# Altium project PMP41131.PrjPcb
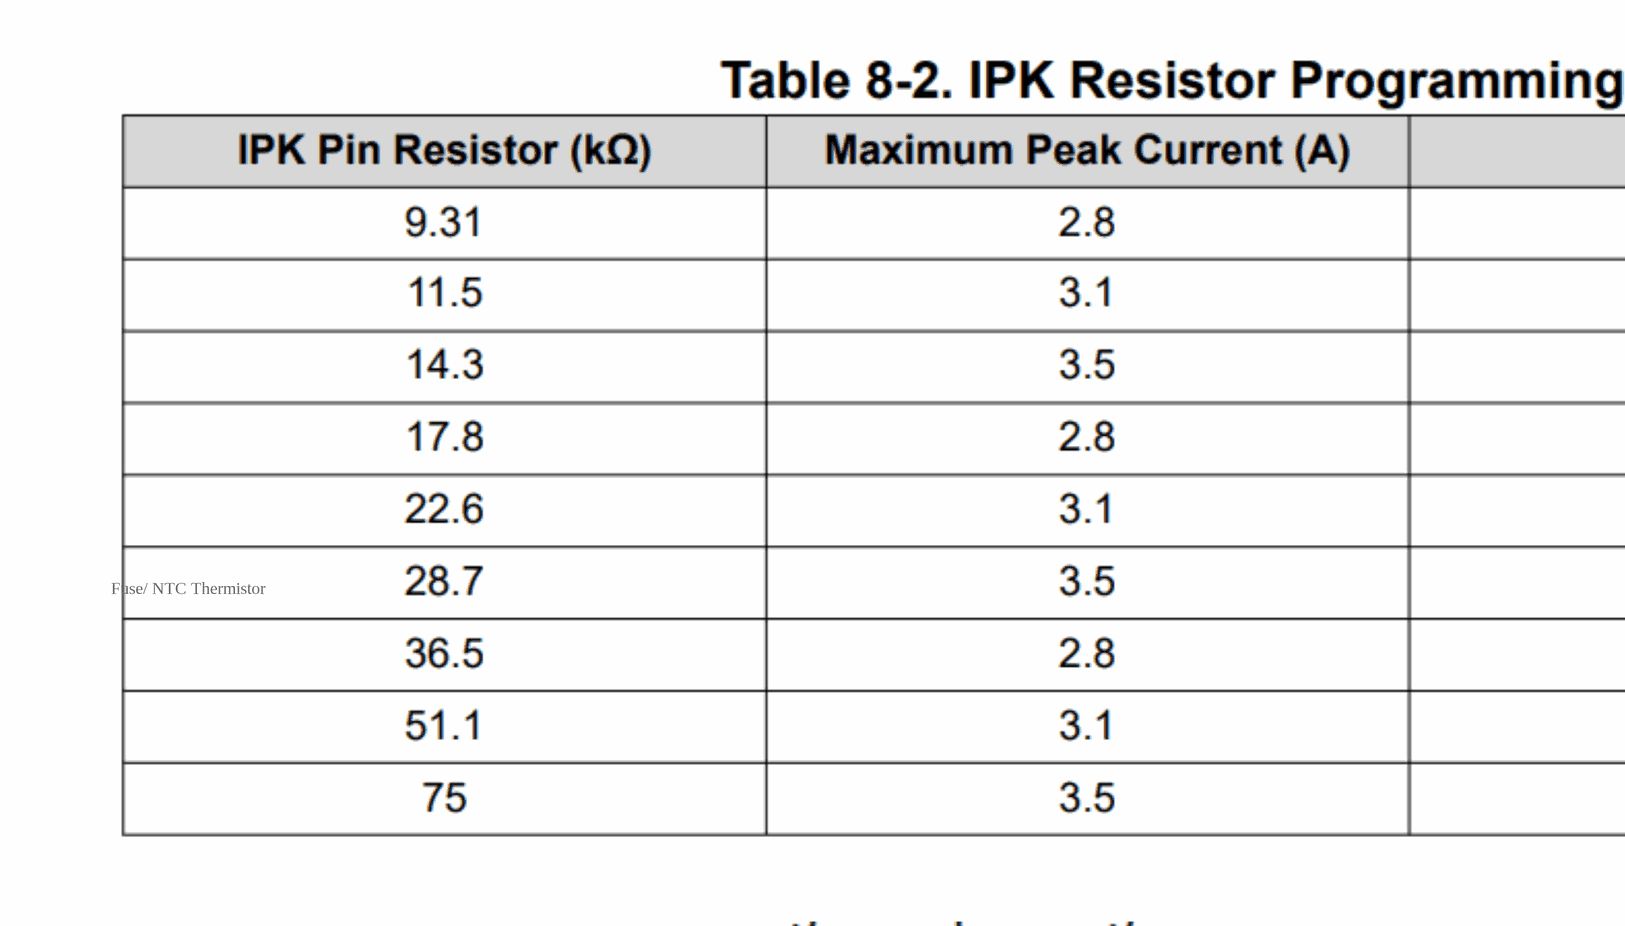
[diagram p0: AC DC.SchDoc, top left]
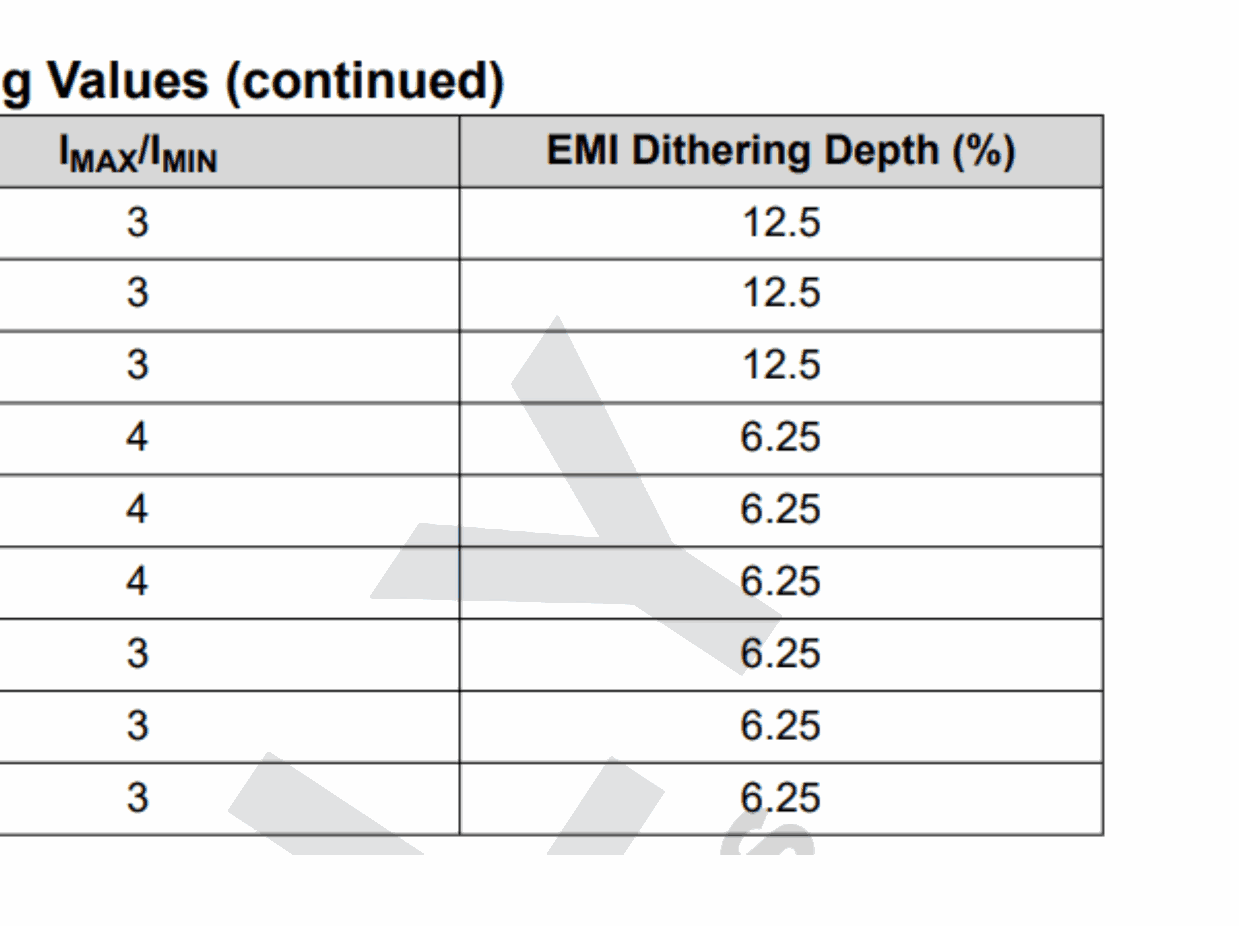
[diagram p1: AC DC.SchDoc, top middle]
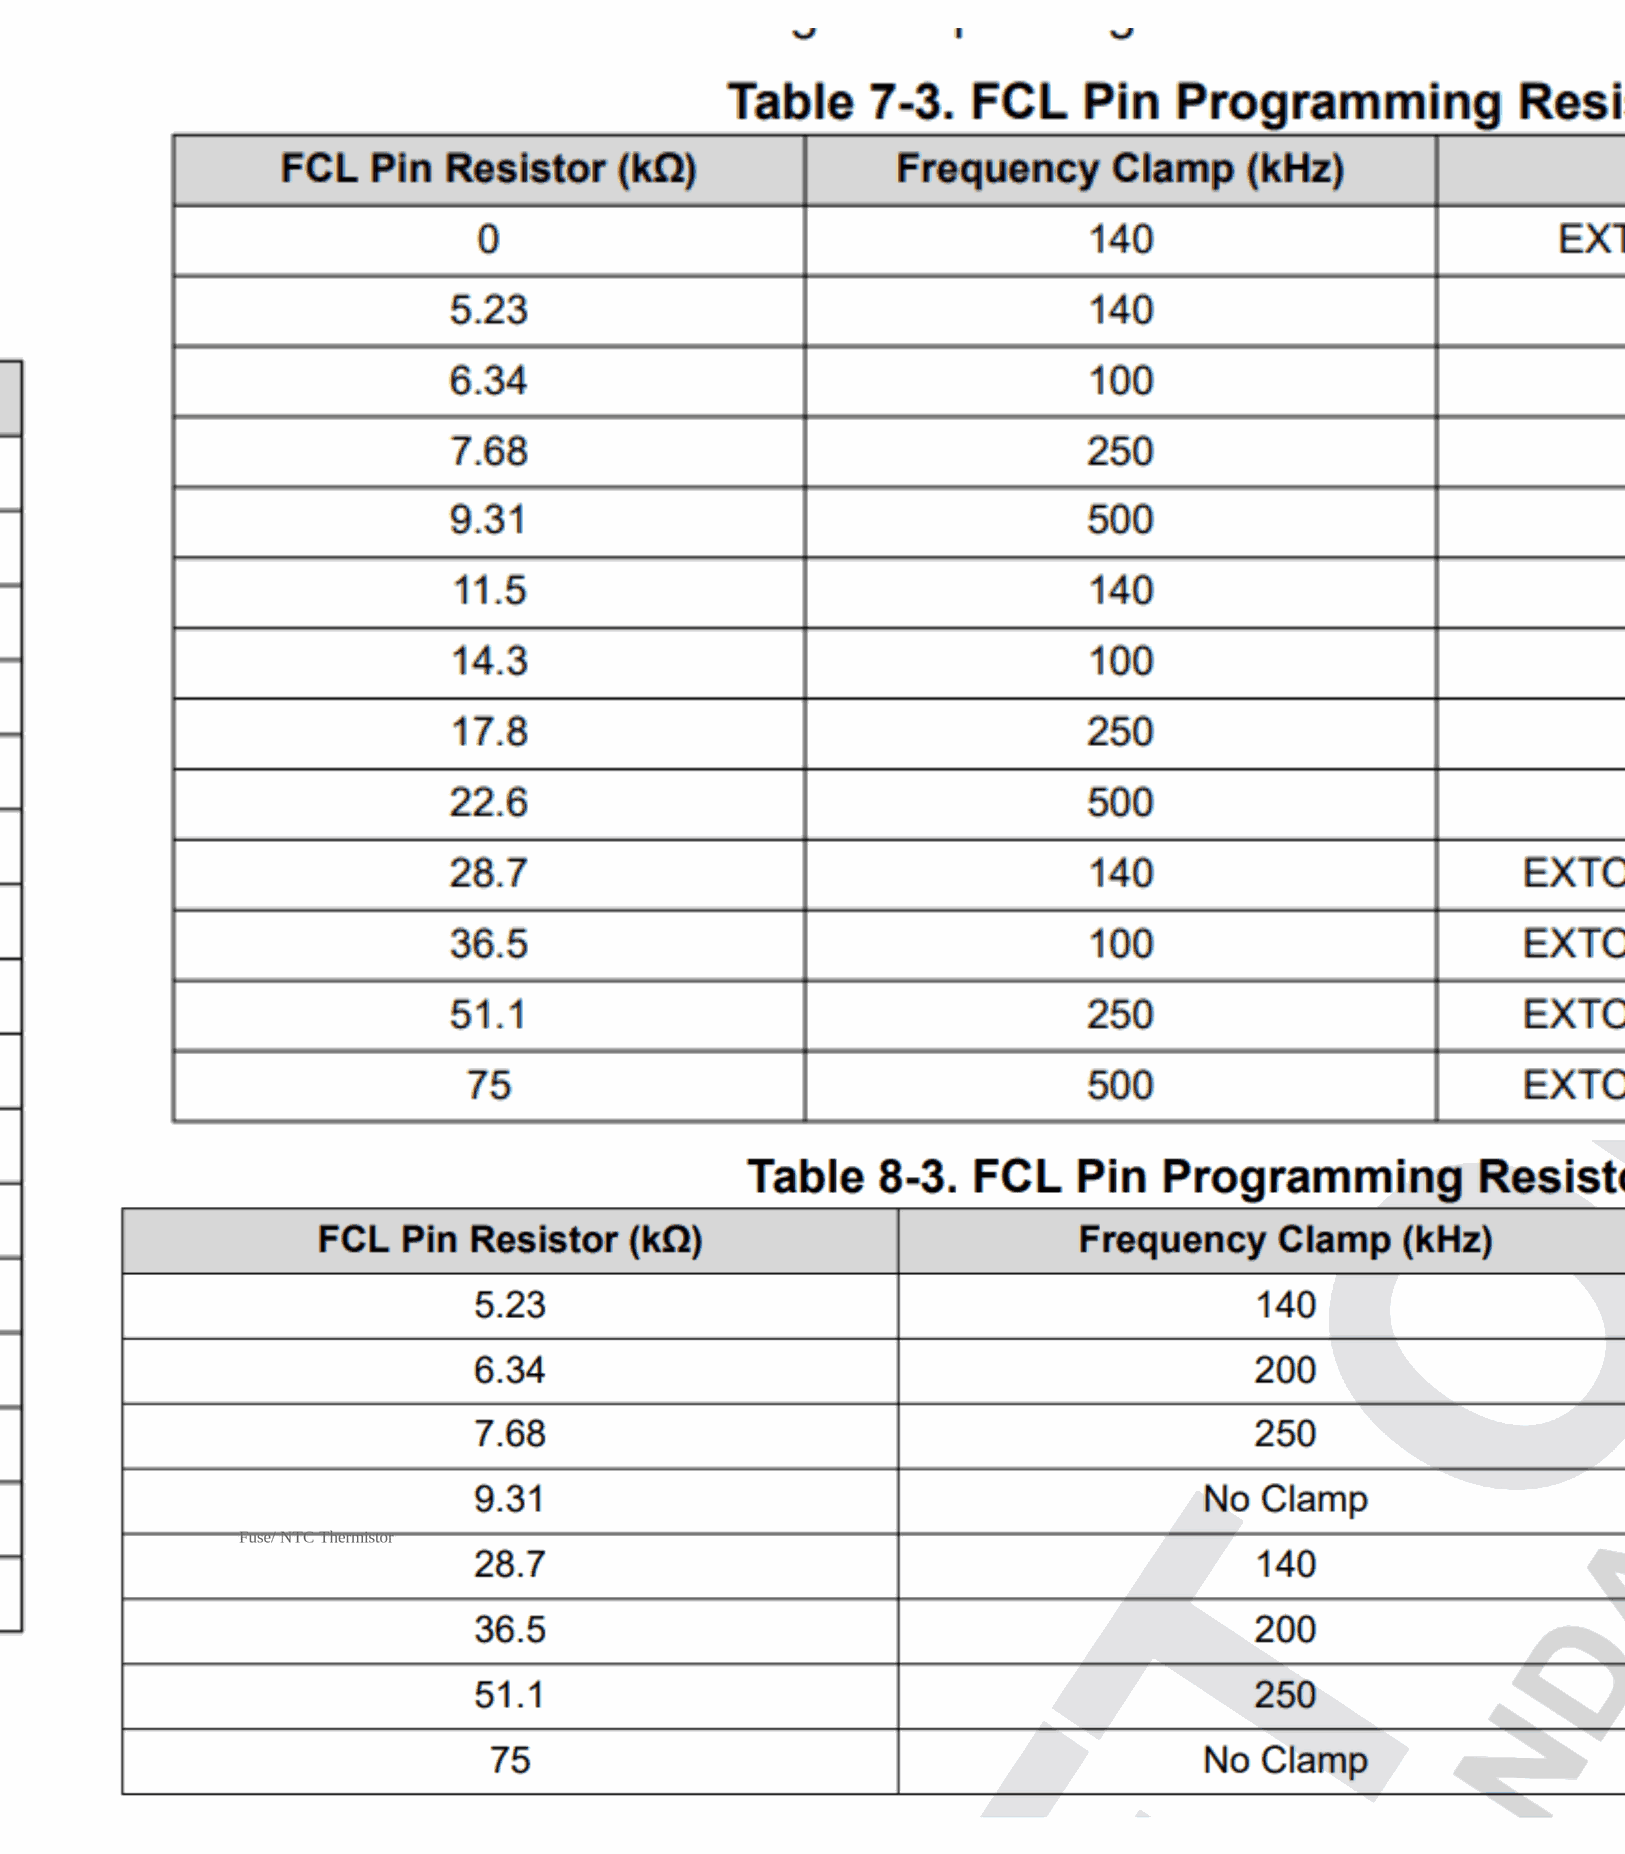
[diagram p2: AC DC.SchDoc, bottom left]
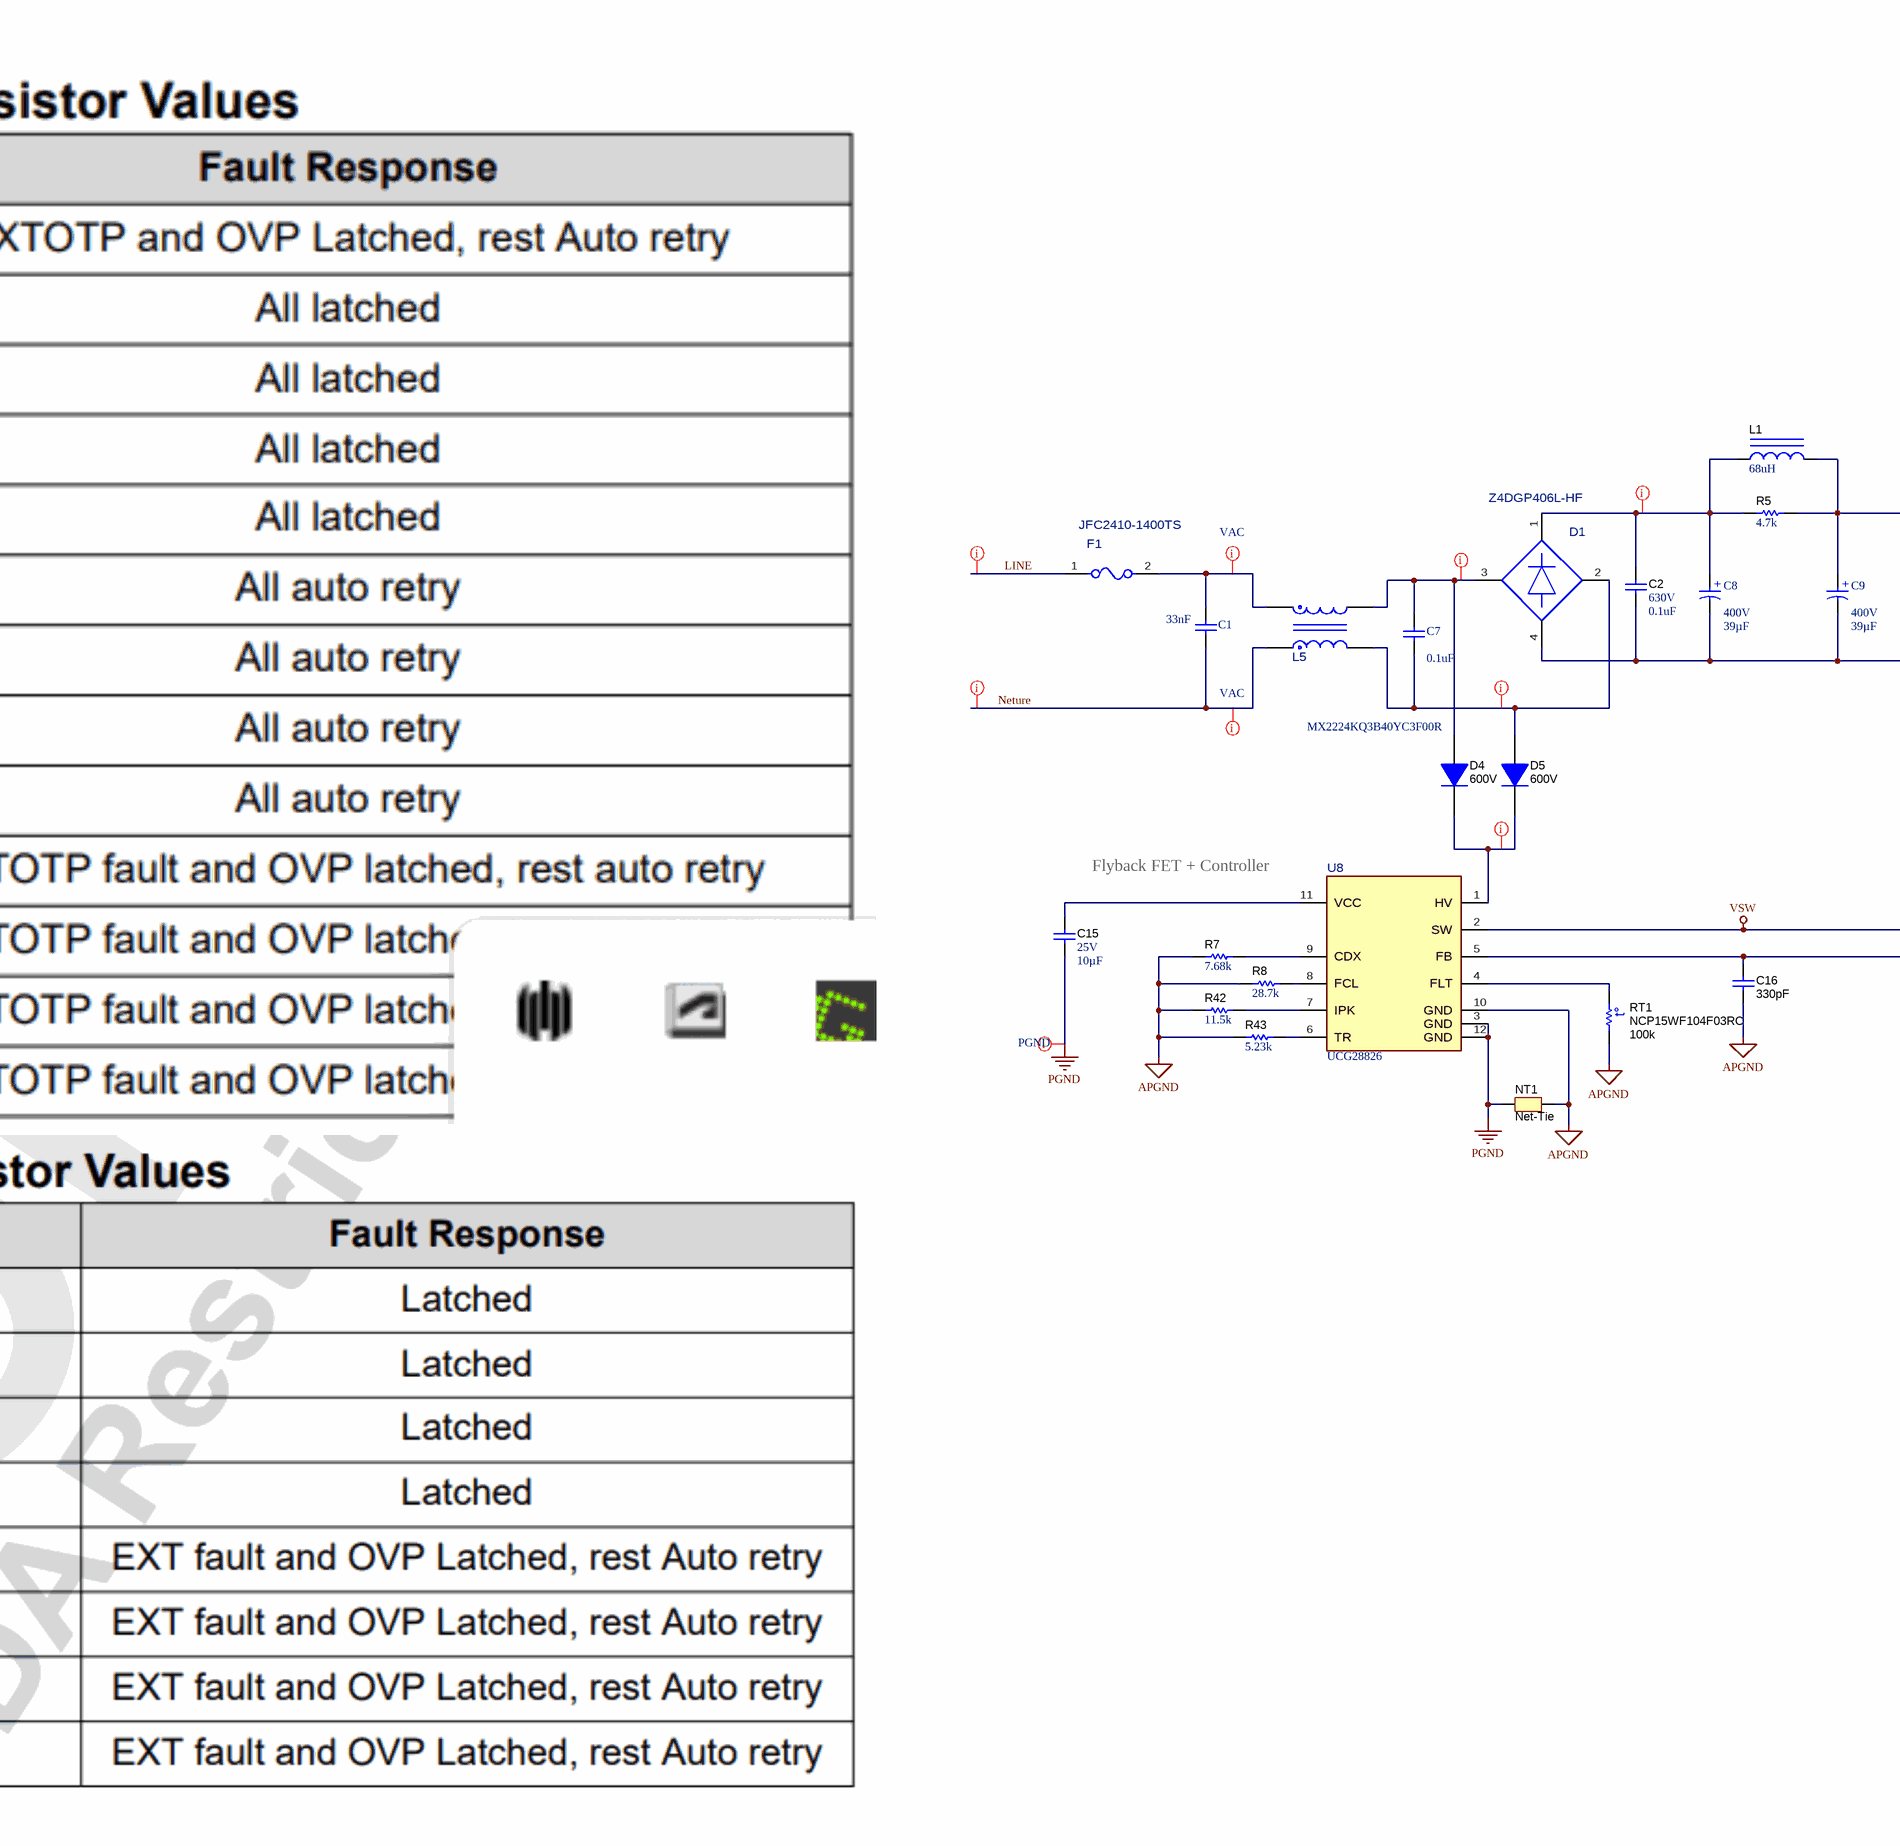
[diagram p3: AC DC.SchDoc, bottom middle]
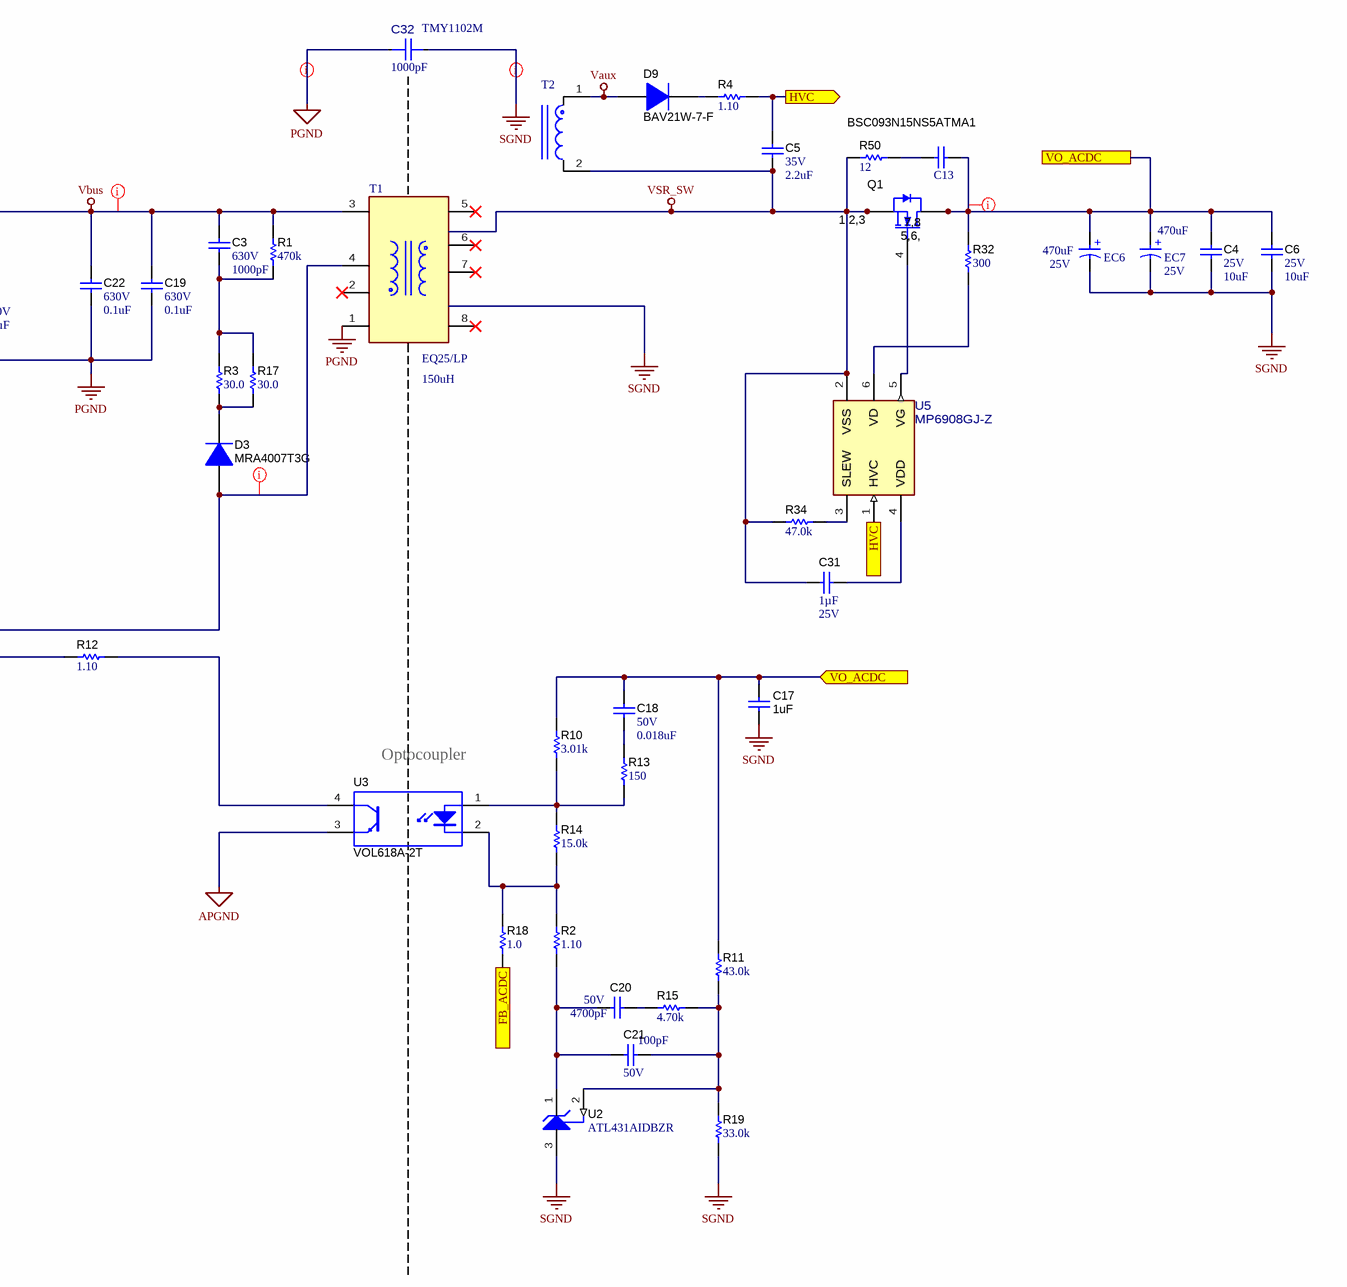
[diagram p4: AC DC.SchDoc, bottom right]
CopyrightYear: 2018; PCB_Layout: Who did the Layout?; PCB_Rev: E1; PRJ_Customer: Public Release; PRJ_Engineer: Enter name of project lead; PRJ_Number: PMP41131; PRJ_Title: Change in menu Project|Project Options|Parameters; SCH_Rev: E1; TechSupport: http://www.ti.com/support; TID: N/A
2 sheets, 93 parts. Net scope: flat (ports and power ports of the same name join across sheets).
Board file: PMP41131.PcbDoc
Sheets:
  AC DC.SchDoc
  USB Type C and PD.SchDoc

## Sheet AC DC.SchDoc
size 431 x 279 mm; Date: Not shown in title block; ApprovedBy: Not shown in title block; CheckedBy: Not shown in title block; Author: Not shown in title block; CompanyName: Not shown in title block; Engineer: Not shown in title block; Organization: Not shown in title block; Address1: Not shown in title block; Address2: Not shown in title block; Address3: Not shown in title block; Address4: Not shown in title block; DocumentNumber: 1; Revision: Use project parameter SCH_Rev; SheetNumber: 1; SheetTotal: 2; PageSetup: Record=PageOptions¦CenterHorizontal=True¦CenterVertical=True¦PrintScale=1.00¦XCorrection=1.00¦YCorrection=1.00¦PrintKind=0¦BorderSize=5000000¦LeftOffset=0¦BottomOffset=0¦Orientation=2¦PaperLength=1000¦PaperWidth=1000¦Scale=100¦PaperSource=15¦PrintQuality=600¦MediaType=1¦DitherType=10¦PaperKind=Letter¦PrintScaleMode=1

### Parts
C1  Cap_F: 33nF  [2220_280]  (hidden comment: SCC2220X333K252T)
C2  VDC_V: 630V  ValueDisplayed: 0.1uF  [1206_180]  (hidden comment: C3216X7T2W104M160AA)
C3  VDC_V: 630V  ValueDisplayed: 1000pF  [1206]  (hidden comment: GRM31BR72J102KW01L)
C4  VDC_V: 25V  ValueDisplayed: 10uF  [0805_HV]  (hidden comment: TMK212BBJ106KG-T)
C5  VDC_V: 35V  ValueDisplayed: 2.2uF  [0603]  (hidden comment: GRM188R6YA225KA12D)
C6  VDC_V: 25V  ValueDisplayed: 10uF  [0805_HV]  (hidden comment: TMK212BBJ106KG-T)
C7  value 0.1uF  PartNumber: MX2224KQ3B40YC3F00R  [XCAP DGXC 0.1UF]  (hidden comment: XCAP DGCX 0.1uF)
C8  Rated Voltage (DC): 400V  Cap_F: 39µF  [400V27uF_Laydown]  (hidden comment: 865230657014)
C9  Rated Voltage (DC): 400V  Cap_F: 39µF  [400V27uF_Laydown]  (hidden comment: 865230657014)
C13  885342207003  [WCAP-CSMH_0805_L2W1.25H0.8_Reflow]  (value not drawn)
C15  VDC_V: 25V  ValueDisplayed: 10µF  [0603S]  (hidden comment: GRM188R61E106KA73D)
C16  ValueDisplayed: 330pF  [0402S]  (hidden comment: GRM155R71H331KA01D)
C17  ValueDisplayed: 1uF  [0603S]  (hidden comment: C1608X7R1E105K080AB)
C18  VDC_V: 50V  ValueDisplayed: 0.018uF  [0402S]  (hidden comment: GRM155R71H183KA12D)
C19  VDC_V: 630V  ValueDisplayed: 0.1uF  [1206_180]  (hidden comment: C3216X7T2W104M160AA)
C20  VDC_V: 50V  ValueDisplayed: 4700pF  [0402S]  (hidden comment: GRM155R71H472KA01D)
C21  VDC_V: 50V  ValueDisplayed: 100pF  [0402S]  (hidden comment: 885012205055)
C22  VDC_V: 630V  ValueDisplayed: 0.1uF  [1206_180]  (hidden comment: C3216X7T2W104M160AA)
C31  Cap_F: 1µF  VDC_V: 25V  [0603S]  (hidden comment: CGA3E1X7R1E105K080AC)
C32  ValueDisplayed: 1000pF  [FP-TMY1102M_7854-MFG]  (hidden comment: TMY1102M)
D1  Z4DGP406L-HF  [FP-Z4DGP406L-HF_SMT_8MM1_10MM5-MFG]
D3  MRA4007T3G  [SMA]
D4  value 600V  [SOD-123]  (hidden comment: ES1JFL)
D5  value 600V  [SOD-123]  (hidden comment: ES1JFL)
D9  BAV21W-7-F  [SOD-123]
EC6  value 470uF  Voltage: 25V  [CE05.5P254L11]  (hidden comment: ECAP_LAYDOWN)
EC7  value 470uF  Voltage: 25V  [CE05.5P254L11]  (hidden comment: ECAP_LAYDOWN)
F1  JFC2410-1400TS  [FP-JFC2410-1400TS_SMT_FUSE_6MM1_2MM6-MFG]
L1  ValueDisplayed: 68uH  [MNR-6045]  (hidden comment: MNR-6045-680MTS)
L5  MDM-9070F-102  [FP-MDM-9070F-102_SMT_CMC_9MM0_7MM0-MFG]  (value not drawn)
NT1  Net-Tie  [Net-Tie_10milWide_30milLong]  (net tie, no BOM)
Q1  BSC093N15NS5ATMA1  [PG-TDSON-8]
R1  ValueDisplayed: 470k  [0805_HV]  (hidden comment: CRCW0805470KJNEA)
R2  ValueDisplayed: 1.10  [0402S]  (hidden comment: CRCW04021R10FKED)
R3  ValueDisplayed: 30.0  [1206]  (hidden comment: RC1206FR-0730RL)
R4  ValueDisplayed: 1.10  [0402S]  (hidden comment: CRCW04021R10FKED)
R5  ValueDisplayed: 4.7k  [1206]  (hidden comment: CRCW12064K70JNEA)
R7  ValueDisplayed: 7.68k  [0402S]  (hidden comment: CRCW04027K68FKED)
R8  ValueDisplayed: 28.7k  [0402S]  (hidden comment: CRCW040228K7FKED)
R10  ValueDisplayed: 3.01k  [0402S]  (hidden comment: CRCW04023K01FKED)
R11  ValueDisplayed: 43.0k  [0603]  (hidden comment: RG1608P-433-B-T5)
R12  ValueDisplayed: 1.10  [0402S]  (hidden comment: CRCW04021R10FKED)
R13  ValueDisplayed: 150  [0402S]  (hidden comment: CRCW0402150RFKED)
R14  ValueDisplayed: 15.0k  [0402S]  (hidden comment: CRCW040215K0FKED)
R15  ValueDisplayed: 4.70k  [0402S]  (hidden comment: RC0402FR-074K7L)
R17  ValueDisplayed: 30.0  [1206]  (hidden comment: RC1206FR-0730RL)
R18  ValueDisplayed: 1.0  [0402S]  (hidden comment: CRCW04021R00JNED)
R19  ValueDisplayed: 33.0k  [0603]  (hidden comment: RG1608P-333-B-T5)
R32  ValueDisplayed: 300  [0603]  (hidden comment: RC0603FR-07300RL)
R34  ValueDisplayed: 47.0k  [0603S]  (hidden comment: CRCW060347K0FKEA)
R42  ValueDisplayed: 11.5k  [0402S]  (hidden comment: CRCW040211K5FKED)
R43  ValueDisplayed: 5.23k  [0402S]  (hidden comment: CRCW04025K23FKED)
R50  ValueDisplayed: 12  [0603]  (hidden comment: CRCW060312R0JNEA)
RT1  NCP15WF104F03RC  value 100k  [0402S]
T1  EQ25/LP  value 150uH  [ATQ23.9_13.8_Remove Flywire]
T2  (no value)  [ATQ23.7_15 4+4 Pin]
U2  ATL431AIDBZR  [DBZ0003A_N]
U3  VOL618A-2T  [SOP254P1020X230-4]
U5  MP6908GJ-Z  [FP-MP6908GJ-Z_TSOT23-6-MFG]
U8  PartNumber: UCG28826  [REZ0012A-MFG]  (hidden comment: UCG28682)

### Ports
FB_ACDC (in), HVC (in), HVC (out), VO_ACDC, VO_ACDC (in)

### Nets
APGND: C16.2 NT1.2 R7.1 R8.1 R42.1 R43.1 RT1.1 U3.3(E) U8.10(GND)
PGND: C2.2 C8.2(N) C9.2(N) C15.2 C19.2 C22.2 C32.1 D1.4(-) NT1.1 T1.1 U8.3(GND) U8.12(GND)
SGND: C4.2 C6.2 C17.1 C32.2 EC6.2(N) EC7.2(N) R19.1 U2.3(ANODE)
Vaux: D9.2(A) T2.1
Vbus: C3.2 C9.1(P) C19.1 C22.1 L1.2 R1.2 R5.2 T1.3
VSR_SW: C5.2 C31.2 Q1.1(S) Q1.2(S) Q1.3(S) R34.1 R50.1 T2.2 U5.2(VSS)
VSW: D3.2(A) T1.4 U8.2(SW)
FB_ACDC: R18.1 ; port FB_ACDC
HVC: C5.1 R4.2 U5.1(HVC) ; port HVC
LINE: F1.1
Neture: C1.2 L5.3
VO_ACDC: C4.1 C6.1 C13.2 C17.2 C18.1 EC6.1(P) EC7.1(P) Q1.5(D) Q1.6(D) Q1.7(D) Q1.8(D) Q1.9(D) R10.2 R11.2 R32.1 ; port VO_ACDC
NetC1_1: C1.1 F1.2 L5.1
NetC2_1: C2.1 C8.1(P) D1.1(+) L1.1 R5.1
NetC3_1: C3.1 R1.1 R3.2 R17.2
NetC7_1: C7.1 D1.3(2_~) D4.2(A) L5.2
NetC7_2: C7.2 D1.2(1_~) D5.2(A) L5.4
NetC13_1: C13.1 R50.2
NetC15_1: C15.1 U8.11(VCC)
NetC16_1: C16.1 R12.1 U8.5(FB)
NetC18_2: C18.2 R13.2
NetC20_1: C20.1 R15.1
NetC20_2: C20.2 C21.2 R2.1 U2.1(CATHODE)
NetC21_1: C21.1 R11.1 R15.2 R19.2 U2.2(REF)
NetC31_1: C31.1 U5.4(VDD)
NetD3_1: D3.1(K) R3.1 R17.1
NetD4_1: D4.1(K) D5.1(K) U8.1(HV)
NetD9_1: D9.1(K) R4.1
NetQ1_4: Q1.4(G) U5.5(VG)
NetR2_2: R2.2 R14.1 R18.2 U3.2(K)
NetR7_2: R7.2 U8.9(CDX)
NetR8_2: R8.2 U8.8(FCL)
NetR10_1: R10.1 R13.1 R14.2 U3.1(A)
NetR12_2: R12.2 U3.4(C)
NetR32_2: R32.2 U5.6(VD)
NetR34_2: R34.2 U5.3(SLEW)
NetR42_2: R42.2 U8.7(IPK)
NetR43_2: R43.2 U8.6(TR)
NetRT1_2: RT1.2 U8.4(FLT)

Not connected (* = marked no-connect by the designer): T1 2* 5* 6* 7* 8*

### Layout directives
net class VAC: LINE, NetC1_1, NetC7_1, NetC7_2, Neture
net class High Voltage: NetC2_1, NetD4_1, Vbus
net class Switch Node: VSW
net class PGND: PGND
net class SGND: SGND, VO_ACDC

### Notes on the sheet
- Fuse/ NTC Thermistor
- Flyback FET + Controller
- (near U3) Optocoupler

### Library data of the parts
C1 = CMP-0112463-1: 2220 SMD, 33nF, 250VAC, Holley Stone; Manufacturer Part Number: 890324023028; Capacitance Tolerance: +/-10%; Dissipation Factor @100kHz: 2%; Dissipation Factor @10kHz: 0.2%; Dissipation Factor @1kHz: 0.1%; Insulation Resistance: 30000MOhm; Match Code: WCAP-FTX2; Pitch: 10mm; Rate of Voltage Rise: 300V/us; Rated Voltage (AC): 275V; Technical Reference: MX2P010224K275ASPB16000
C2 C19 C22 = CMP-0008729-1: CAP, CERM, 0.1 uF, 450 V, +/- 20%, X7T, 1206; Manufacturer: TDK; TaMin_C: -55°C; Polarized: N; SizeAreaWB_mm2: 10.92; Value1: Unknown; U/M: EA; Value: 0.1uF; TaMax_C: 125°C; SizeZ_mm: 1.8; SizeX_mm: 3.2; SizeY_mm: 1.6; Cap_Case: 1206; Value2: 450V; SizeArea_mm2: 5.12; Cap_F: 100nF; AEC Category: Q200
C3 = CMP-0008909-2: CAP, CERM, 1000 pF, 630 V, +/- 10%, X7R, 1206; Manufacturer: MuRata; TaMin_C: -55°C; Polarized: N; SizeAreaWB_mm2: 10.92; Value1: Unknown; U/M: EA; Value: 1000pF; TaMax_C: 125°C; SizeZ_mm: 1.35; SizeX_mm: 3.2; SizeY_mm: 1.6; SizeArea_mm2: 5.12; Cap_F: 1nF; AEC Category: Q200
C4 C6 = CMP-0008414-2: CAP, CERM, 10 uF, 25 V, +/- 10%, X5R, 0805; Manufacturer: Taiyo Yuden; TaMin_C: -55°C; Polarized: N; SizeAreaWB_mm2: 6.75; Value1: Unknown; U/M: EA; Value: 10uF; TaMax_C: 85°C; SizeZ_mm: 1.45; SizeX_mm: 2; SizeY_mm: 1.25; Cap_Case: 0805; SizeArea_mm2: 2.5; Cap_F: 10µF; AEC Category: Q200
C5 = CMP-0007356-4: CAP, CERM, 2.2 uF, 35 V, +/- 10%, X5R, 0603; Manufacturer: MuRata; TaMin_C: -55°C; Polarized: N; SizeAreaWB_mm2: 4.68; Value1: Unknown; U/M: EA; Value: 2.2uF; TaMax_C: 85°C; SizeZ_mm: 1; SizeX_mm: 1.6; SizeY_mm: 0.8; SizeArea_mm2: 1.28; Cap_F: 2.2µF; AEC Category: Q200
C8 C9 = 865230657014: Aluminum Electrolytic Capacitor, Radial, THT, D10 x H20-mm, 39µF, 400V; Manufacturer: Yongming; PartNumber: KCXE2502G470MF; Capacitance Tolerance: +0%/-40%; Case/Size Code: D10 x H20mm; Dissipation Factor: 15%; Endurance: 2000h; Leakage Current: 264uA; Match Code: WCAP-ATG5; Ripple Current: 200mA; Technical Reference: ATJE1602203400DSPA7B0LR; Value: 39uF
C13 = CMP-0112285-1: WCAP-CSMH Multilayer Ceramic Chip Capacitor, Mid and High Voltage, size 0805, X7R Class II, 1nF, 200VDC; Manufacturer: Wurth Elektronik; Capacitance Tolerance: 10%; Case/Size Code: 0805; Dissipation Factor: 2.5%; Insulation Resistance: 10GOhm; Rated Voltage (DC): 200V; Technical Reference: X7R0805102K200DFCT10000
C15 = CMP-0860569-1: CAP, CERM, 10 µF, 25 V,+/- 10%, X5R, 0603; Manufacturer: MuRata; SizeZ_mm: 1; AEC Category: Q200; AEC Qualified: N; TaMin_C: -55°C; Cap_Case: 0603; SizeY_mm: 0.8; SizeAreaWB_mm2: 4.68; SizeArea_mm2: 1.28; TaMax_C: 85°C; SizeX_mm: 1.6; Value: 10uF; U/M: EA
C16 = CMP-0006687-2: CAP, CERM, 330 pF, 50 V, +/- 10%, X7R, 0402; Manufacturer: MuRata; TaMin_C: -55°C; Polarized: N; SizeAreaWB_mm2: 3; Value1: Unknown; U/M: EA; Value: 330pF; TaMax_C: 125°C; SizeZ_mm: 0.6; SizeX_mm: 1; SizeY_mm: 0.5; Cap_Case: 0402; Value2: 50V; AEC Category: Q200
C17 = CMP-0007040-4: CAP, CERM, 1 µF, 25 V, +/- 10%, X7R, 0603; Manufacturer: TDK; Polarized: N; CompType: Capacitor; Value: 1uF; U/M: EA; Cap_F: 1µF; Value1: Unknown; VDC_V: 25V; TaMin_C: -55°C; TaMax_C: 125°C; Cap_Case: 0603; AEC Category: Q200; SizeArea_mm2: 1.28; SizeAreaWB_mm2: 4.68; SizeX_mm: 1.6; SizeY_mm: 0.8; SizeZ_mm: 1
C18 = CMP-0006681-2: CAP, CERM, 0.018 uF, 50 V, +/- 10%, X7R, 0402; Manufacturer: MuRata; TaMin_C: -55°C; Polarized: N; SizeAreaWB_mm2: 3; Value1: Unknown; U/M: EA; TaMax_C: 125°C; SizeZ_mm: 0.6; SizeX_mm: 1; SizeY_mm: 0.5; Cap_Case: 0402; Cap_F: 18nF; AEC Category: Q200
C20 = CMP-0006692-2: CAP, CERM, 4700 pF, 50 V, +/- 10%, X7R, 0402; Manufacturer: MuRata; TaMin_C: -55°C; Polarized: N; SizeAreaWB_mm2: 3; Value1: Unknown; U/M: EA; Value: 4700pF; TaMax_C: 125°C; SizeZ_mm: 0.6; SizeX_mm: 1; SizeY_mm: 0.5; Cap_Case: 0402; Cap_F: 4.7nF; AEC Category: Q200
C21 = CMP-0006230-2: CAP, CERM, 100 pF, 50 V, +/- 10%, X7R, 0402; Manufacturer: Wurth Elektronik; TaMin_C: -55°C; Polarized: N; SizeAreaWB_mm2: 3; Value1: Unknown; U/M: EA; Value: 100pF; TaMax_C: 125°C; SizeZ_mm: 0.6; SizeX_mm: 1; SizeY_mm: 0.5; Cap_Case: 0402; AEC Category: Q200
C31 = CMP-0076705-1: CAP, CERM, 1 µF, 25 V,+/- 10%, X7R, AEC-Q200 Grade 1, 0603; Manufacturer: TDK; SizeAreaWB_mm2: 4.68; SizeArea_mm2: 1.28; AEC Qualified: Y; AEC Category: Q200; Value: 1uF; TaMax_C: 125°C; SizeZ_mm: 1.0; AEC Grade: 1; Polarized: N; TaMin_C: -55°C; SizeY_mm: 0.8; U/M: EA; SizeX_mm: 1.6; Cap_Case: 1.6x0.8x0.8mm
C32 = CMP-0125632-1: SMD-Y1 a.c. ceramic capacitor 1000pF 20% 400VAC 7.8x5.4x2.45mm; Manufacturer: SICHUAN TRX TECHNOLOGY; AEC Qualified: No; Cap_F: 1nF; SizeZ_mm: 2.45mm; TempCo: +22/-56%; VAC: 400V; Standoff Height: 0.02mm; Temperature Characteristic: Y5U; Value: 1nF
D1 = CMP-0120719-1: Bridge Rectifier Single Phase Standard 600 V Surface Mount Z4-D; Manufacturer: Comchip; AEC Qualified: No; SizeZ_mm: 1.45mm; TJmax_C: 175°C; Vf_V: 600V; Cap_F: 45pF; Forward Current: 4A; Max Surge Forward Current: 150A; Peak Reverse Current: 0.08uA
D3 = CMP-0077082-2: Diode, Standard Recovery Rectifier, 1000 V, 1 A, AEC-Q101, SMA; Manufacturer: ON Semiconductor; Value2: 1.1V; TJmax_C: 175°C; SizeX_mm: 5.59; Green_Lifecycle: Active; Value1: 1A; Green_REACh: Passed; AEC Qualified: Y; AEC Category: Q101; SizeArea_mm2: 16.3228; SizeY_mm: 2.92; SizeAreaWB_mm2: 37.3428; Value: 1000V; RJC_CperW: 16.2; SizeZ_mm: 2.87; Vr_V: 1kV
D4 D5 = CMP-0029032-2: Diode, Switching, 600 V, 1 A, SOD-123; Manufacturer: ON Semiconductor; SizeY_mm: 1.7; Io_A: 1A; SizeAreaWB_mm2: 13.095; SizeArea_mm2: 6.545; Vf_V: 1V; TJmax_C: 150°C; SizeX_mm: 3.85; SizeZ_mm: 1.35; Green_Lifecycle: Active; Green_REACh: Passed
D9 = CMP-0029031-2: Diode, Switching, 200 V, 0.2 A, SOD-123; Manufacturer: Diodes Inc.; Green_REACh: Passed; SizeArea_mm2: 6.545; TJmax_C: 150°C; Value2: 1.25V; Io_A: 200mA; SizeAreaWB_mm2: 13.095; SizeY_mm: 1.7; Value: 200V; Green_Lifecycle: Active; SizeX_mm: 3.85; SizeZ_mm: 1.35; AEC Category: Q101; Value1: 0.2A
EC6 EC7 = ECAP_LAYDOWN: 25V/470uF D5.5*11mm
F1 = CMP-0124957-1: 50A SMD Fuse 4A 250V 250V SMD Disposable fuses ROHS; Manufacturer: Shenzhen JDT Fuse; MeltingTyp: 34.4A2Sec; SizeZ_mm: 2.8mm; Fuse Speed: Slow; AEC Qualified: No; Res_ohm: 0.0186Ω
L1 = CMP-0060059-2: Inductor, Wirewound, Ferrite, 68 uH, 0.9 A, 0.33 ohm, SMD; Manufacturer: Mag Layers; Isat: 1A @ 30% inductance drop; Irms: 0.9A @ 40C rise; Green_Lifecycle: Not Set; SizeAreaWB_mm2: 64; DCR_ohm: 0.33; Green_REACh: Incomplete; Value: 68uH; Imax_A: 900mA; SizeZ_mm: 4.5; SizeX_mm: 6; Value2: 0.9A; SizeArea_mm2: 36; Ind_H: 68µH; AEC Category: Q200
L5 = CMP-0124709-1: Wire Wound Common Mode Choke 1000Ohm @ 100MHz, 4A IDC, 9.0x7.0x4.8mm SMT; Manufacturer: MAG-AGA; DCR_ohm: 13m; SizeZ_mm: 4.8mm; AEC Qualified: No; Impedance At Frequency: 1000Ω @ 100MHz
NT1 = CMP-0078142-6: Single point connection between nets.
Q1 = CMP-0001046-2: MOSFET, N-CH, 150 V, 87 A, PG-TDSON-8; Alternate Manufacturer: None; Manufacturer: Infineon Technologies; SizeZ_mm: 1.12; ChType: N; Value2: 33 nC; VdsMax_V: 150V; SizeX_mm: 5.99; SizeY_mm: 4.9; Vgs_V: 20V; QgTyp_nC: 33; Value: 150V; SizeArea_mm2: 29.351; AEC Category: Q101; IdsMax_A: 87A; SizeAreaWB_mm2: 55.131; U/M: EA
R1 = CMP-0020554-3: RES, 470 k, 5%, 0.125 W, AEC-Q200 Grade 0, 0805; Manufacturer: Vishay-Dale; Power_W: 125mW; TempCo: 200 ppm/C; Value: 470k; EIA_Code: E24; SizeX_mm: 2; SizeY_mm: 1.25; SizeZ_mm: 1.45; Value2: 0.125W; SizeArea_mm2: 2.5; AEC Qualified: Y; VDC_V: 150V; AEC Category: Q200; AEC Grade: 0
R2 R4 R12 = CMP-0026133-1: RES, 1.10, 1%, 0.063 W, 0402; Manufacturer: Vishay-Dale; Power_W: 63mW; TempCo: 100 ppm/C; Value_Code: 1R10; U/M: EA; Value: 1.10; EIA_Code: E96; Res_ohm: 1.1; SizeX_mm: 1; SizeY_mm: 0.5; SizeZ_mm: 0.6; Value2: 0.063W; VDC_V: 50V; AEC Category: Q200
R3 R17 = CMP-0018196-2: RES, 30.0, 1%, 0.25 W, 1206; Manufacturer: Yageo America; Power_W: 250mW; TempCo: 100 ppm/C; Value_Code: 30R0; U/M: EA; Value: 30.0; Res_ohm: 30; SizeX_mm: 3.2; SizeY_mm: 1.6; SizeZ_mm: 1.35; Value2: 0.25W; SizeArea_mm2: 5.12; VDC_V: 200V; AEC Category: Q200
R5 = CMP-0018689-2: RES, 4.7 k, 5%, 0.25 W, 1206; Manufacturer: Vishay-Dale; Power_W: 250mW; TempCo: 200 ppm/C; Value_Code: 4k70; U/M: EA; Value: 4.7k; EIA_Code: E24; SizeX_mm: 3.2; SizeY_mm: 1.6; SizeZ_mm: 1.35; Value2: 0.25W; SizeArea_mm2: 5.12; VDC_V: 200V; AEC Category: Q200
R7 = CMP-0026556-2: RES, 7.68 k, 1%, 0.063 W, AEC-Q200 Grade 0, 0402; Manufacturer: Vishay-Dale; Power_W: 63mW; TempCo: 100 ppm/C; Value_Code: 7k68; Value: 7.68k; EIA_Code: E96; SizeX_mm: 1; SizeY_mm: 0.5; SizeZ_mm: 0.6; Value2: 0.063W; AEC Qualified: Y; VDC_V: 50V; AEC Category: Q200; AEC Grade: 0
R8 = CMP-0026220-2: RES, 28.7 k, 1%, 0.063 W, AEC-Q200 Grade 0, 0402; Manufacturer: Vishay-Dale; Power_W: 63mW; TempCo: 100 ppm/C; Value_Code: 28k7; Value: 28.7k; EIA_Code: E96; SizeX_mm: 1; SizeY_mm: 0.5; SizeZ_mm: 0.6; Value2: 0.063W; AEC Qualified: Y; VDC_V: 50V; AEC Category: Q200; AEC Grade: 0
R10 = CMP-0026329-2: RES, 3.01 k, 1%, 0.063 W, AEC-Q200 Grade 0, 0402; Manufacturer: Vishay-Dale; Power_W: 63mW; TempCo: 100 ppm/C; Value_Code: 3k01; Value: 3.01k; EIA_Code: E96; SizeX_mm: 1; SizeY_mm: 0.5; SizeZ_mm: 0.6; Value2: 0.063W; AEC Qualified: Y; VDC_V: 50V; AEC Category: Q200; AEC Grade: 0
R11 = CMP-0023550-2: RES, 43.0 k, 0.1%, 0.1 W, 0603; Manufacturer: Susumu Co Ltd; Power_W: 100mW; TempCo: 25 ppm/C; Value_Code: 43k0; U/M: EA; Value: 43.0k; Res_ohm: 43k; SizeX_mm: 1.6; SizeY_mm: 0.8; SizeZ_mm: 1; Value2: 0.1W; SizeArea_mm2: 1.28; VDC_V: 75V; AEC Category: Q200
R13 = CMP-0026022-3: RES, 150, 1%, 0.063 W, AEC-Q200 Grade 0, 0402; Manufacturer: Vishay-Dale; Power_W: 63mW; TempCo: 100 ppm/C; Value_Code: 150R; Value: 150; EIA_Code: E96; SizeX_mm: 1; SizeY_mm: 0.5; SizeZ_mm: 0.6; Value2: 0.063W; AEC Qualified: Y; VDC_V: 50V; AEC Category: Q200; AEC Grade: 0
R14 = CMP-0026027-3: RES, 15.0 k, 1%, 0.063 W, AEC-Q200 Grade 0, 0402; Manufacturer: Vishay-Dale; Power_W: 63mW; TempCo: 100 ppm/C; Value_Code: 15k0; Value: 15.0k; EIA_Code: E96; Res_ohm: 15k; SizeX_mm: 1; SizeY_mm: 0.5; SizeZ_mm: 0.6; Value2: 0.063W; AEC Qualified: Y; VDC_V: 50V; AEC Category: Q200; AEC Grade: 0
R15 = CMP-0026739-1: RES, 4.70 k, 1%, 0.0625 W, 0402; Manufacturer: Yageo America; Power_W: 62.5mW; TempCo: 100 ppm/C; Value_Code: 4k70; U/M: EA; Value: 4.70k; Res_ohm: 4.7k; SizeX_mm: 1; SizeY_mm: 0.5; SizeZ_mm: 0.6; AEC Qualified: N; VDC_V: 50V; AEC Category: Q200
R18 = CMP-0026866-2: RES, 1.0, 5%, 0.063 W, 0402; Manufacturer: Vishay-Dale; Power_W: 63mW; TempCo: 200 ppm/C; Value_Code: 1R00; U/M: EA; Value: 1.0; EIA_Code: E24; Res_ohm: 1; SizeY_mm: 0.5; SizeZ_mm: 0.6; Value2: 0.063W; VDC_V: 50V; AEC Category: Q200
R19 = CMP-0023520-3: RES, 33.0 k, 0.1%, 0.1 W, 0603; Manufacturer: Susumu Co Ltd; Power_W: 100mW; TempCo: 25 ppm/C; Value_Code: 33k0; U/M: EA; Value: 33.0k; Res_ohm: 33k; SizeX_mm: 1.6; SizeY_mm: 0.8; SizeZ_mm: 1; Value2: 0.1W; SizeArea_mm2: 1.28; VDC_V: 75V; AEC Category: Q200
R32 = CMP-0023013-5: RES, 300, 1%, 0.1 W, 0603; Manufacturer: Yageo; Power_W: 100mW; TempCo: 100 ppm/C; Value_Code: 300R; Value: 300; SizeX_mm: 1.6; SizeY_mm: 0.8; SizeZ_mm: 1; Value2: 0.1W; SizeArea_mm2: 1.28; AEC Qualified: N; VDC_V: 75V; AEC Category: Q200; SizeAreaWB_mm2: 4.68
R34 = CMP-0022438-1: RES, 47.0 k, 1%, 0.1 W, AEC-Q200 Grade 0, 0603; Manufacturer: Vishay-Dale; Power_W: 100mW; TempCo: 100 ppm/C; Value_Code: 47k0; U/M: EA; Value: 47.0k; Res_ohm: 47k; SizeX_mm: 1.6; SizeY_mm: 0.8; SizeZ_mm: 1; Value2: 0.1W; SizeArea_mm2: 1.28; AEC Qualified: Y; VDC_V: 75V; AEC Grade: 0; AEC Category: Q200
R42 = CMP-0025977-1: RES, 11.5 k, 1%, 0.063 W, 0402; Manufacturer: Vishay-Dale; Power_W: 63mW; TempCo: 100 ppm/C; Value_Code: 11k5; U/M: EA; Value: 11.5k; EIA_Code: E96; SizeX_mm: 1; SizeY_mm: 0.5; SizeZ_mm: 0.6; Value2: 0.063W; VDC_V: 50V; AEC Category: Q200
R43 = CMP-0026464-2: RES, 5.23 k, 1%, 0.063 W, AEC-Q200 Grade 0, 0402; Manufacturer: Vishay-Dale; Power_W: 63mW; TempCo: 100 ppm/C; Value_Code: 5k23; Value: 5.23k; EIA_Code: E96; SizeX_mm: 1; SizeY_mm: 0.5; SizeZ_mm: 0.6; Value2: 0.063W; AEC Qualified: Y; VDC_V: 50V; AEC Category: Q200; AEC Grade: 0
R50 = CMP-0025712-2: RES, 12, 5%, 0.1 W, 0603; Manufacturer: Vishay-Dale; Power_W: 100mW; TempCo: 200 ppm/C; Value_Code: 12R0; U/M: EA; Value: 12; EIA_Code: E24; SizeX_mm: 1.6; SizeY_mm: 0.8; SizeZ_mm: 1; Value2: 0.1W; SizeArea_mm2: 1.28; VDC_V: 75V; AEC Category: Q200
RT1 = CMP-0002353-2: Thermistor NTC, 100k ohm, 1%, 0402; Manufacturer: MuRata; TaMax_C: 125°C; SizeX_mm: 1; SizeY_mm: 0.5; TaMin_C: -40°C; Power_W: 100mW; SizeZ_mm: 0.6; SizeAreaWB_mm2: 3; U/M: EA
T1 = ATQ23_15 4_4 Pin: EQ25/LP, Lm=150uH
T2 = Aux winding
U2 = CMP-0066199-1: 2.5V Low Iq Adjustable Precision Shunt Regulator, DBZ0003A (SOT-23-3); Alternate Manufacturer: Texas Instruments; SizeAreaWB_mm2: 14.0; U/M: EA; SizeZ_mm: 1.12; SizeX_mm: 2.5; SizeY_mm: 3.0; SizeArea_mm2: 7.5; CompType: IC
U3 = CMP-0006160-3: Optocoupler, 5 kV, 63-125% CTR, SMT; Manufacturer: Vishay-Semiconductor; CTR (Max): 125%; SizeAreaWB_mm2: 74.42; CTR (Min): 63%; SizeZ_mm: 2.3; SizeX_mm: 10.2; SizeY_mm: 4.1; SizeArea_mm2: 41.82; Voltage_Isolation_Vrms: 5kV
U5 = CMP-0086802-1: FAST TURN-OFF INTELLIGENT RECTIF; Manufacturer: Monolithic Power Systems; SizeZ_mm: 1mm
U8 = CMP-0121635-2: Manufacturer: Texas Instruments; SizeZ_mm: 1mm; Standoff Height: 0mm; AEC Category: Q200; CompType: IC

## Sheet USB Type C and PD.SchDoc
size 431 x 279 mm; Date: Not shown in title block; ApprovedBy: Not shown in title block; CheckedBy: Not shown in title block; Author: Not shown in title block; CompanyName: Not shown in title block; Engineer: Not shown in title block; Organization: Not shown in title block; Address1: Not shown in title block; Address2: Not shown in title block; Address3: Not shown in title block; Address4: Not shown in title block; DocumentNumber: 2; Revision: Use project parameter SCH_Rev; SheetNumber: 2; SheetTotal: 2; PageSetup: Record=PageOptions¦CenterHorizontal=True¦CenterVertical=True¦PrintScale=1.00¦XCorrection=1.00¦YCorrection=1.00¦PrintKind=0¦BorderSize=5000000¦LeftOffset=0¦BottomOffset=0¦Orientation=2¦PaperLength=1000¦PaperWidth=1000¦Scale=100¦PaperSource=15¦PrintQuality=600¦MediaType=1¦DitherType=10¦PaperKind=Letter¦PrintScaleMode=1
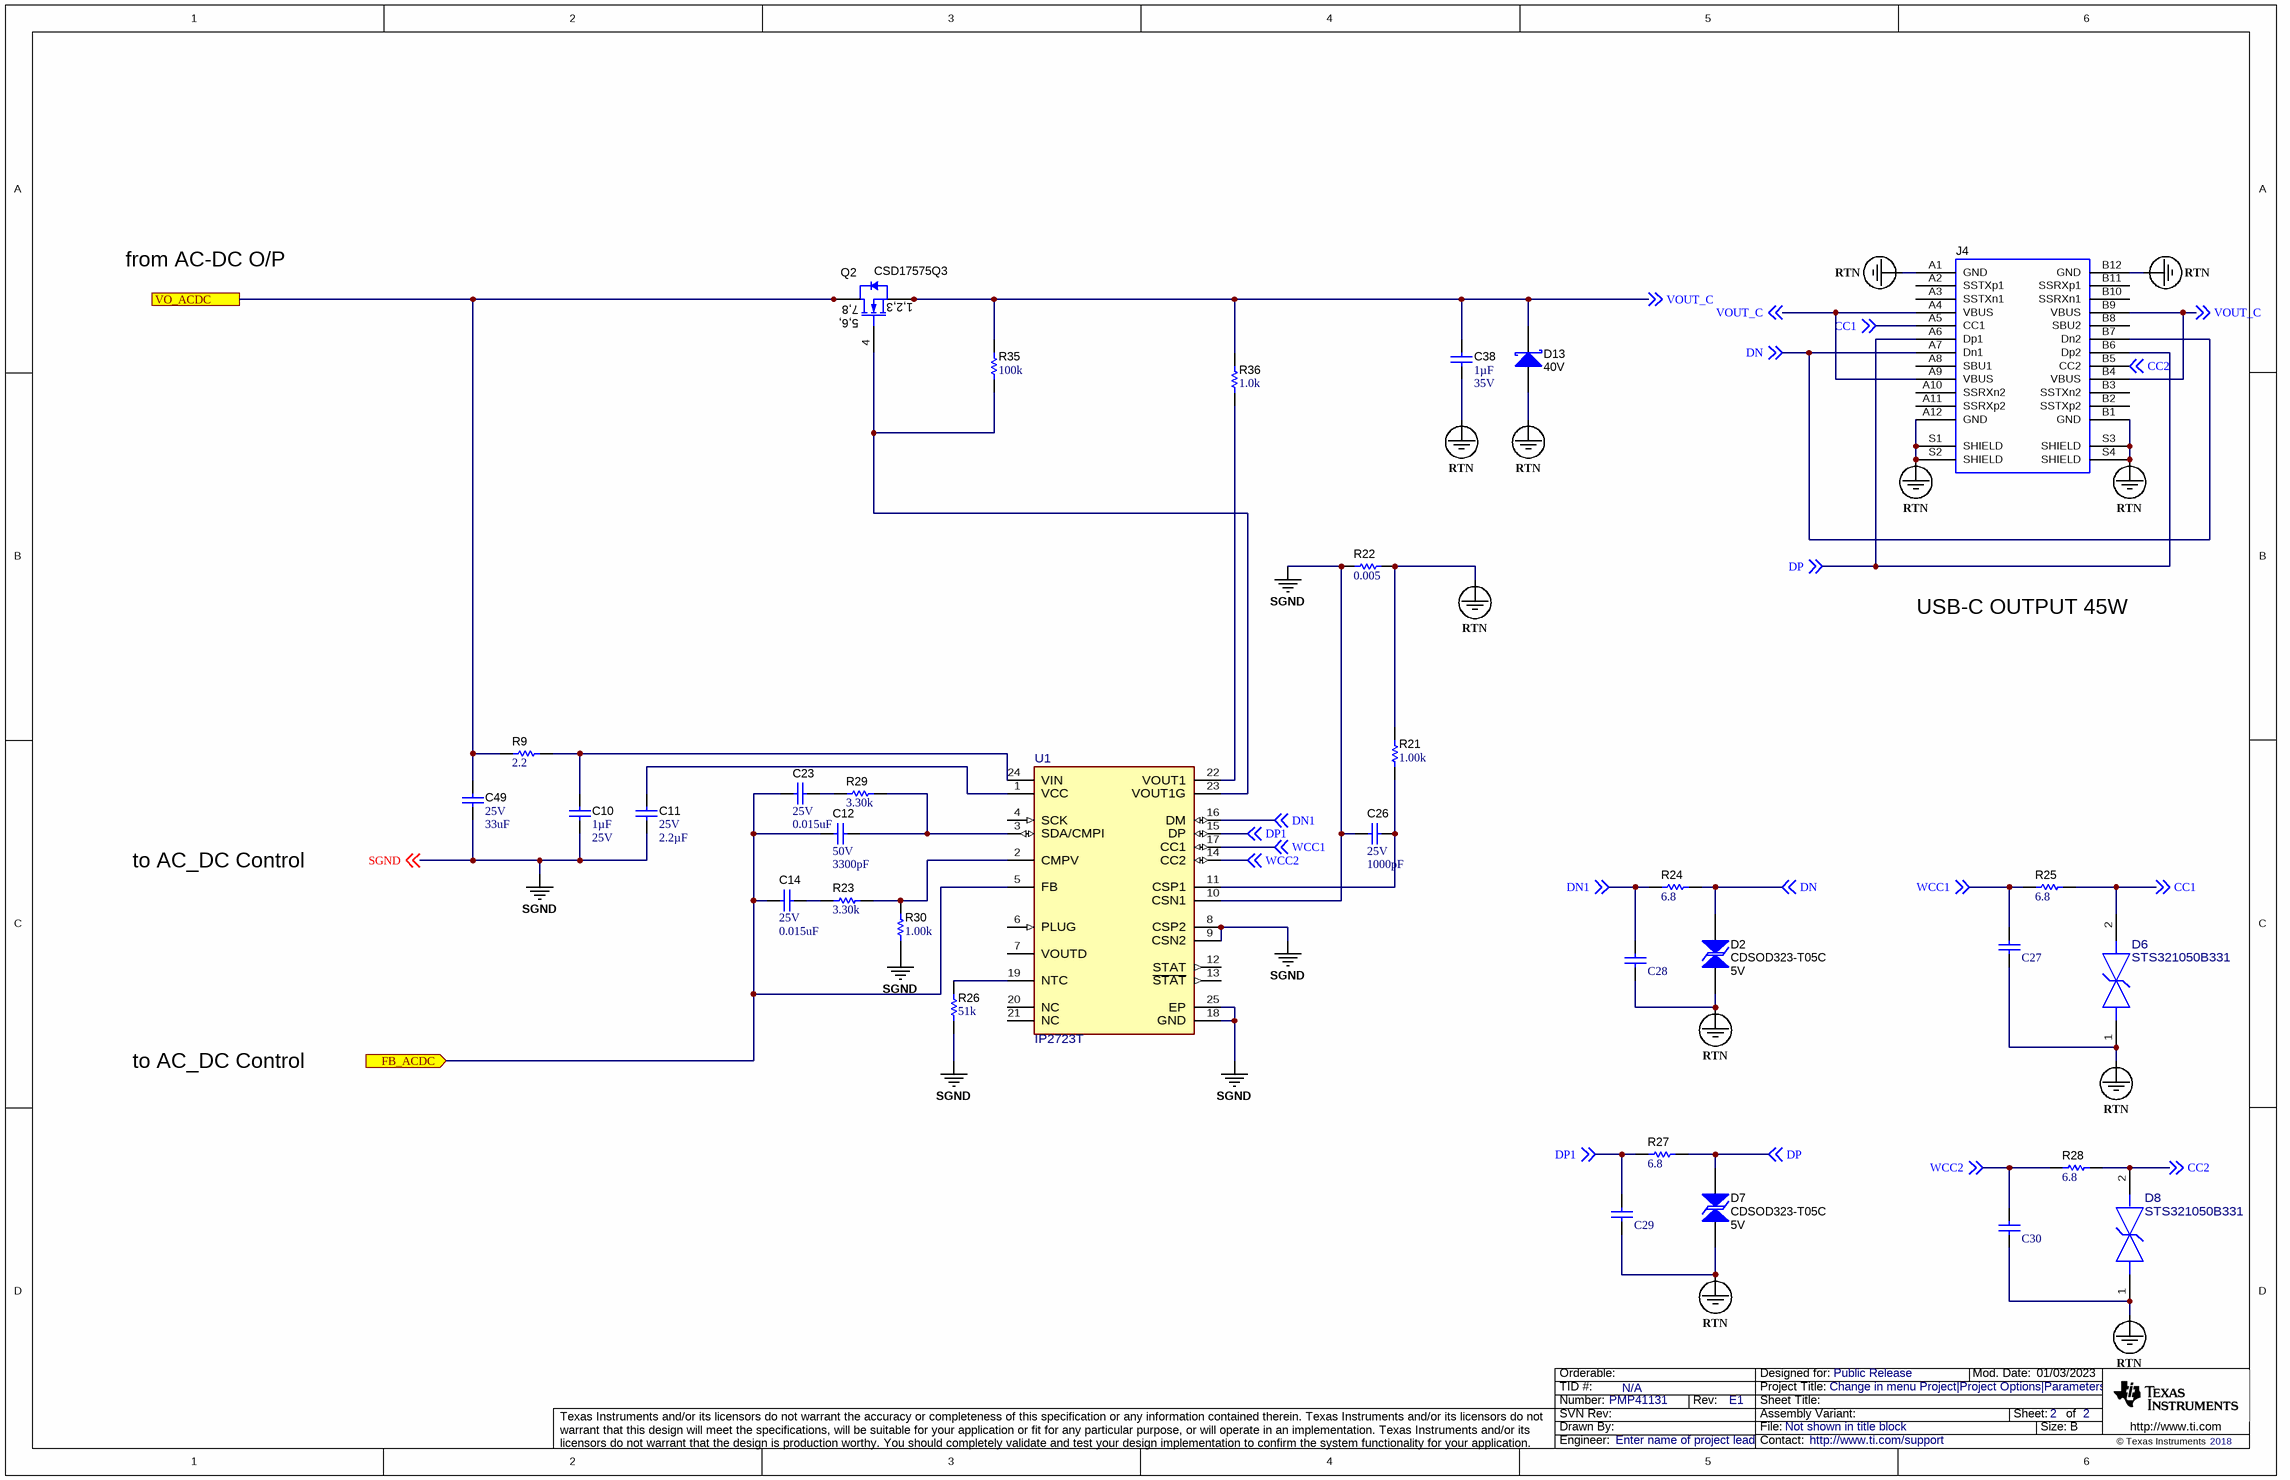
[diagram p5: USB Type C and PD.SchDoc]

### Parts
C10  Cap_F: 1µF  VDC_V: 25V  [0603S]  (hidden comment: GCM188R71E105KA64D)
C11  VDC_V: 25V  ValueDisplayed: 2.2µF  [0402S]  (hidden comment: GRM155R61E225ME15D)
C12  VDC_V: 50V  ValueDisplayed: 3300pF  [0402S]  (hidden comment: GRM155R71H332KA01D)
C14  VDC_V: 25V  ValueDisplayed: 0.015uF  [0402S]  (hidden comment: GRM155R71E153KA61D)
C23  VDC_V: 25V  ValueDisplayed: 0.015uF  [0402S]  (hidden comment: GRM155R71E153KA61D)
C26  VDC_V: 25V  ValueDisplayed: 1000pF  [0402S]  (hidden comment: C0402C102J3RACTU)
C27  885012205042  [WCAP-CSGP_0402_L1W0.5H0.5]  (value not drawn)
C28  885012205042  [WCAP-CSGP_0402_L1W0.5H0.5]  (value not drawn)
C29  885012205042  [WCAP-CSGP_0402_L1W0.5H0.5]  (value not drawn)
C30  885012205042  [WCAP-CSGP_0402_L1W0.5H0.5]  (value not drawn)
C38  Cap_F: 1µF  VDC_V: 35V  [0603S]  (hidden comment: C1608X7R1V105K080AC)
C49  VDC_V: 25V  ValueDisplayed: 33uF  [1206_180]  (hidden comment: C3216X5R1E336M160AC)
D2  CDSOD323-T05C  value 5V  [SOD-323-Bi]
D6  STS321050B331  [FP-STS321050B331_SOD-323-MFG]
D7  CDSOD323-T05C  value 5V  [SOD-323-Bi]
D8  STS321050B331  [FP-STS321050B331_SOD-323-MFG]
D13  value 40V  [SOD-523]  (hidden comment: RB521SM-40T2R)
J4  DX07S024JJ2R1300  [JAE_DX07S024JJ2R1300]  (value not drawn)
Q2  CSD17575Q3  [DQG0008A]
R9  ValueDisplayed: 2.2  [0402S]  (hidden comment: CRCW04022R20JNED)
R21  ValueDisplayed: 1.00k  [0402S]  (hidden comment: RC0402FR-071KL)
R22  ValueDisplayed: 0.005  [1206]  (hidden comment: CSR1206-0R005F1)
R23  ValueDisplayed: 3.30k  [0402S]  (hidden comment: ERJ-2RKF3301X)
R24  ValueDisplayed: 6.8  [0402S]  (hidden comment: CRCW04026R80JNED)
R25  ValueDisplayed: 6.8  [0402S]  (hidden comment: CRCW04026R80JNED)
R26  ValueDisplayed: 51k  [0402]  (hidden comment: CRCW040251K0JNED)
R27  ValueDisplayed: 6.8  [0402S]  (hidden comment: CRCW04026R80JNED)
R28  ValueDisplayed: 6.8  [0402S]  (hidden comment: CRCW04026R80JNED)
R29  ValueDisplayed: 3.30k  [0402S]  (hidden comment: ERJ-2RKF3301X)
R30  ValueDisplayed: 1.00k  [0402S]  (hidden comment: MCR01MZPF1001)
R35  ValueDisplayed: 100k  [0402S]  (hidden comment: RC0402FR-07100KL)
R36  ValueDisplayed: 1.0k  [0603S]  (hidden comment: ESR03EZPJ102)
U1  IP2723T  [FP-IP2723TH_QFN24-IPC_C]

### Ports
FB_ACDC (in), VO_ACDC

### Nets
RTN: C27.1 C28.1 C29.1 C30.1 C38.2 D2.1 D6.1 D7.1 D8.1 D13.2(A) J4.A1(GND) J4.A12(GND) J4.B1(GND) J4.B12(GND) J4.S1(SHIELD) J4.S2(SHIELD) J4.S3(SHIELD) J4.S4(SHIELD) R21.2 R22.2
SGND: C10.2 C11.2 C26.2 C49.2 R22.1 R26.1 R30.1 U1.8(CSP2) U1.9(CSN2) U1.10(CSN1) U1.18(GND) U1.25(EP) ; off-sheet SGND
CC1: D6.2 J4.A5(CC1) R25.2 ; off-sheet CC1
CC2: D8.2 J4.B5(CC2) R28.2 ; off-sheet CC2
DN: D2.2 J4.A7(Dn1) J4.B7(Dn2) R24.2 ; off-sheet DN
DN1: C28.2 R24.1 U1.16(DM) ; off-sheet DN1
DP: D7.2 J4.A6(Dp1) J4.B6(Dp2) R27.2 ; off-sheet DP
DP1: C29.2 R27.1 U1.15(DP) ; off-sheet DP1
FB_ACDC: C12.1 C14.2 C23.2 U1.5(FB) ; port FB_ACDC
VO_ACDC: C49.1 Q2.5(D) Q2.6(D) Q2.7(D) Q2.8(D) Q2.9(D) R9.1 ; port VO_ACDC
VOUT_C: C38.1 D13.1(K) J4.A4(VBUS) J4.A9(VBUS) J4.B4(VBUS) J4.B9(VBUS) Q2.1(S) Q2.2(S) Q2.3(S) R35.2 R36.2 ; off-sheet VOUT_C
WCC1: C27.2 R25.1 U1.17(CC1) ; off-sheet WCC1
WCC2: C30.2 R28.1 U1.14(CC2) ; off-sheet WCC2
NetC10_1: C10.1 R9.2 U1.24(VIN)
NetC11_1: C11.1 U1.1(VCC)
NetC12_2: C12.2 R29.2 U1.3(SDA/CMPI)
NetC14_1: C14.1 R23.1
NetC23_1: C23.1 R29.1
NetC26_1: C26.1 R21.1 U1.11(CSP1)
NetQ2_4: Q2.4(G) R35.1 U1.23(VOUT1G)
NetR23_2: R23.2 R30.2 U1.2(CMPV)
NetR26_2: R26.2 U1.19(NTC)
NetR36_1: R36.1 U1.22(VOUT1)

Not connected (* = marked no-connect by the designer): J4 A2(SSTXp1) A3(SSTXn1) A8(SBU1) A10(SSRXn2) A11(SSRXp2) B2(SSTXp2) B3(SSTXn2) B8(SBU2) B10(SSRXn1) B11(SSRXp1); U1 4(SCK) 6(PLUG) 7(VOUTD) 12(STAT) 13(~{STAT}) 20(NC) 21(NC)

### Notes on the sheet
- from AC-DC O/P
- USB-C OUTPUT 45W
- to AC_DC Control

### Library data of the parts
C10 = CMP-0007139-1: CAP, CERM, 1 uF, 25 V, +/- 10%, X7R, AEC-Q200 Grade 1, 0603; Manufacturer: MuRata; TaMin_C: -55°C; Polarized: N; SizeAreaWB_mm2: 4.68; Value1: Unknown; U/M: EA; Value: 1uF; TaMax_C: 125°C; SizeZ_mm: 1; SizeX_mm: 1.6; SizeY_mm: 0.8; Cap_Case: 0603; SizeArea_mm2: 1.28; AEC Qualified: Y; AEC Category: Q200
C11 = CMP-0081010-1: CAP, CERM, 2.2 µF, 25 V,+/- 20%, X5R, 0402; Manufacturer: MuRata; SizeAreaWB_mm2: 3; SizeArea_mm2: 0.5; AEC Qualified: N; AEC Category: Q200; Value: 2.2uF; TaMax_C: 85°C; SizeZ_mm: 0.6; TaMin_C: -55°C; U/M: EA; SizeX_mm: 1; Cap_Case: 0402
C12 = CMP-0006688-2: CAP, CERM, 3300 pF, 50 V, +/- 10%, X7R, 0402; Manufacturer: MuRata; TaMin_C: -55°C; Polarized: N; SizeAreaWB_mm2: 3; Value1: Unknown; U/M: EA; Value: 3300pF; TaMax_C: 125°C; SizeZ_mm: 0.6; SizeX_mm: 1; SizeY_mm: 0.5; Cap_Case: 0402; Cap_F: 3.3nF; AEC Category: Q200
C14 C23 = CMP-0006661-1: CAP, CERM, 0.015 uF, 25 V, +/- 10%, X7R, 0402; Manufacturer: MuRata; TaMin_C: -55°C; Polarized: N; SizeAreaWB_mm2: 3; Value1: Unknown; U/M: EA; TaMax_C: 125°C; SizeZ_mm: 0.6; SizeX_mm: 1; SizeY_mm: 0.5; Cap_Case: 0402; Cap_F: 15nF; AEC Category: Q200
C26 = CMP-0006234-2: CAP, CERM, 1000 pF, 25 V, +/- 5%, X7R, 0402; Manufacturer: Kemet; TaMin_C: -55°C; Polarized: N; SizeAreaWB_mm2: 3; Value1: Unknown; U/M: EA; Value: 1000pF; TaMax_C: 125°C; SizeZ_mm: 0.6; SizeX_mm: 1; SizeY_mm: 0.5; Cap_Case: 0402; Cap_F: 1nF; AEC Category: Q200
C27-C30 = CMP-0104610-1: WCAP-CSGP Multilayer Ceramic Chip Capacitor, General Purpose, size 0402, X7R, 470pF, 25VDC; Manufacturer: Wurth Elektronik; Capacitance Tolerance: +/-10%; Case/Size Code: 0402; Dissipation Factor: 3.5%; Insulation Resistance: 10GOhm; Rated Voltage (DC): 25V; Technical Reference: X7R0402471K025DFCT10000
C38 = CMP-0007052-2: CAP, CERM, 1 uF, 35 V, +/- 10%, X7R, 0603; Manufacturer: TDK; TaMin_C: -55°C; Polarized: N; SizeAreaWB_mm2: 4.68; Value1: Unknown; U/M: EA; Value: 1uF; TaMax_C: 125°C; SizeZ_mm: 1; SizeX_mm: 1.6; SizeY_mm: 0.8; Cap_Case: 0603; SizeArea_mm2: 1.28; AEC Category: Q200
C49 = CMP-0008655-1: CAP, CERM, 33 uF, 25 V, +/- 20%, X5R, 1206; Manufacturer: TDK; TaMin_C: -55°C; ESR_ohm: 2.648m; Polarized: N; SizeAreaWB_mm2: 10.92; Value1: 0.002648 ohm; U/M: EA; Value: 33uF; TaMax_C: 85°C; SizeZ_mm: 1.8; SizeX_mm: 3.2; SizeY_mm: 1.6; SizeArea_mm2: 5.12; Cap_F: 33µF; IRMS_A: 4.4586A; AEC Category: Q200
D2 D7 = CMP-0006065-2: Diode, TVS, Bi, 5 V, SOD323, 2-Leads, Body 1.9x1.45mm, No Polarity Mark; Manufacturer: Bourns; Ppk: 350W; AEC Category: Q101
D6 D8 = CMP-0092592-1: 18V Clamp 22A (8/20µs) Ipp Tvs Diode Surface Mount SOD-323; Manufacturer: Eaton; ValueDisplayed: 33pF; Breakdown Voltage: 5.5V; Number Of Channels: 1; SizeZ_mm: 1mm; AEC Qualified: No; Ppk: 400W; VRWM: 5V; TJmax_C: +125°C; Direction: Bidirectional
D13 = CMP-0074704-3: Diode, Schottky, 40 V, 0.2 A, SOD-523; Manufacturer: Rohm; SizeAreaWB_mm2: 5.13; SizeZ_mm: 0.65; AEC Category: Q101; AEC Qualified: N; Vf_V: 540mV; Io_A: 200mA; Value2: 0.54V; SizeArea_mm2: 1.53; TJmax_C: 150°C; Value1: 0.2A; SizeX_mm: 1.7; SizeY_mm: 0.9
J4 = CMP-0085712-2: Receptacle, USB 3.1 Type C, R/A, Gold, SMT; Manufacturer: JAE Electronics; Current_A: 1.25A; Gender: Female; Voltage_V: 20V; Pitch_mm: 0.5; Row_Count: 2
Q2 = CMP-0000587-1: MOSFET, N-CH, 30 V, 60 A, DQG0008A (VSON-CLIP-8); Manufacturer: Texas Instruments; Alternate Manufacturer: None; U/M: EA; ChType: N; Value: 30V; Value1: 0.003; Rdson45_ohm: 3.2m; Value2: 23 nC; QgTyp_nC: 23; Vgs_V: 20V; IdsMax_A: 60A; AEC Category: Q101; SizeZ_mm: 1.1; SizeX_mm: 3.3; SizeArea_mm2: 10.89; SizeAreaWB_mm2: 18.49
R9 = CMP-0026898-1: RES, 2.2, 5%, 0.063 W, 0402; Manufacturer: Vishay-Dale; Power_W: 63mW; TempCo: 200 ppm/C; Value_Code: 2R20; U/M: EA; Value: 2.2; EIA_Code: E24; SizeX_mm: 1; SizeY_mm: 0.5; SizeZ_mm: 0.6; Value2: 0.063W; VDC_V: 50V; AEC Category: Q200
R21 = CMP-0026725-1: RES, 1.00 k, 1%, 0.0625 W, 0402; Manufacturer: Yageo America; Power_W: 62.5mW; TempCo: 100 ppm/C; Value_Code: 1k00; U/M: EA; Value: 1.00k; EIA_Code: E96; Res_ohm: 1k; SizeX_mm: 1; SizeY_mm: 0.5; SizeZ_mm: 0.6; AEC Qualified: N; VDC_V: 50V; AEC Category: Q200
R22 = CMP-0078497-1: RES, 0.005, 1%, 1 W, 1206; Manufacturer: Riedon; Power_W: 1W; TempCo: 50 ppm/C; Value_Code: 5L000; Value: 0.005; EIA_Code: E96; Res_ohm: 5m; SizeX_mm: 3.2; SizeY_mm: 1.6; SizeZ_mm: 1.35; SizeArea_mm2: 5.12; AEC Qualified: N; AEC Category: Q200
R23 R29 = CMP-0026695-1: RES, 3.30 k, 1%, 0.1 W, AEC-Q200 Grade 0, 0402; Manufacturer: Panasonic; Power_W: 100mW; TempCo: 100 ppm/C; Value_Code: 3k30; U/M: EA; Value: 3.30k; Res_ohm: 3.3k; SizeX_mm: 1; SizeY_mm: 0.5; SizeZ_mm: 0.6; Value2: 0.1W; AEC Qualified: Y; VDC_V: 50V; AEC Grade: 0; AEC Category: Q200
R24 R25 R27 R28 = CMP-0026970-1: RES, 6.8, 5%, 0.063 W, 0402; Manufacturer: Vishay-Dale; Power_W: 63mW; TempCo: 200 ppm/C; Value_Code: 6R80; U/M: EA; Value: 6.8; EIA_Code: E24; SizeX_mm: 1; SizeY_mm: 0.5; SizeZ_mm: 0.6; Value2: 0.063W; VDC_V: 50V; AEC Category: Q200
R26 = CMP-0026945-1: RES, 51 k, 5%, 0.063 W, 0402; Manufacturer: Vishay-Dale; Power_W: 63mW; TempCo: 200 ppm/C; Value_Code: 51k0; U/M: EA; Value: 51k; EIA_Code: E24; SizeX_mm: 1; SizeY_mm: 0.5; SizeZ_mm: 0.6; Value2: 0.063W; VDC_V: 50V; AEC Category: Q200
R30 = CMP-0026716-1: RES, 1.00 k, 1%, 0.063 W, 0402; Manufacturer: Rohm; Power_W: 63mW; TempCo: 100 ppm/C; Value_Code: 1k00; U/M: EA; Value: 1.00k; EIA_Code: E96; Res_ohm: 1k; SizeX_mm: 1; SizeY_mm: 0.5; SizeZ_mm: 0.6; Value2: 0.063W; AEC Qualified: N; VDC_V: 50V; AEC Category: Q200
R35 = CMP-0026721-1: RES, 100 k, 1%, 0.0625 W, 0402; Manufacturer: Yageo America; Power_W: 62.5mW; TempCo: 100 ppm/C; U/M: EA; Value: 100k; EIA_Code: E96; SizeX_mm: 1; SizeY_mm: 0.5; SizeZ_mm: 0.6; AEC Qualified: N; VDC_V: 50V; AEC Category: Q200
R36 = CMP-0084244-1: RES, 1.0 k, 5%, 0.25 W, AEC-Q200 Grade 0, 0603; Manufacturer: Rohm; Power_W: 250mW; TempCo: 200 ppm/C; SizeAreaWB_mm2: 4.68; Value_Code: 1k00; Value: 1.0k; EIA_Code: E24; Res_ohm: 1k; SizeX_mm: 1.6; SizeY_mm: 0.8; SizeZ_mm: 1; Value2: 0.25W; SizeArea_mm2: 1.28; AEC Qualified: Y; AEC Grade: 0; AEC Category: Q200
U1 = CMP-0124680-1: Integrate multiple protocols, fast charging protocol IC for USBC port; Manufacturer: Injoinic; PartNumber: IP2723TH; SizeZ_mm: 0.8mm; AEC Qualified: No; Max Supply Voltage: 25V; Min Supply Voltage: 3V; Standoff Height: 0.02mm; TaMax_C: +85°C; TaMin_C: -40°C; TJmax_C: +150°C

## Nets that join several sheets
SGND: AC DC (8 pins), USB Type C and PD (12 pins)
FB_ACDC: AC DC (R18.1), USB Type C and PD (C12.1 C14.2 C23.2 U1.5)
VO_ACDC: AC DC (15 pins), USB Type C and PD (7 pins)

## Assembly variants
001: not fitted C1 C20 C21 R2 R11 R15 R19 R30 U2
